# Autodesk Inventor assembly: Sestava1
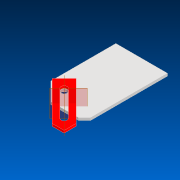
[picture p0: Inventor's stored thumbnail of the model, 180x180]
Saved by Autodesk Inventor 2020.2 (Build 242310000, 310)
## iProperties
Created: 2021-01
Part Number: Sestava1
Document SubType Name: Assembly
Designer: Pavel
UlozenoKym: navara
Author: Pavel
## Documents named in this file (3)
- C:\Users\navara\Desktop\Nová složka\Sestava1.iam
- C:\Users\navara\Desktop\Nová složka\Deska.ipt
- C:\Users\navara\Desktop\Nová složka\Posuv.ipt
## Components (2 placed, 2 different names)
1. Deska:1 — Proti sobě:1, Úhel:1, Proti sobě:2, Proti sobě:3
2. Posuv:1 — Proti sobě:1, Úhel:1, Proti sobě:2, Proti sobě:3
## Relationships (4: Mate 3, Angle 1)
- Proti sobě:1 [Mate]: Deska:1 ↔ Posuv:1
- Úhel:1 [Angle]: Deska:1 ↔ Posuv:1
- Proti sobě:2 [Mate]: Deska:1 ↔ Posuv:1
- Proti sobě:3 [Mate]: Deska:1 ↔ Posuv:1
